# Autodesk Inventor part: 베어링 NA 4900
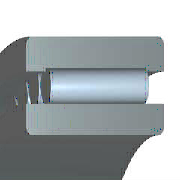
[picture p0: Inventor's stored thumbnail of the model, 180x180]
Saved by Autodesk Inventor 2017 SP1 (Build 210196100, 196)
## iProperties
Created: 2021-07
Part Number: 베어링 NA 4900
Material: 강철, 연강
Description: 니들 롤러 베어링 - 경계 치수 및 공차
Document SubType Name: Modeling
Standard: KS B 2029
Designer: mdu
Standards Organization: KS
Language: ko-KR
Size Designation: NA 4900 - 10 x 22 x 13
Categories: <MemberInstance><Categories><Category DisplayName="샤프트 부품" InternalName="7f7aeb1f-a693-4053-b835-cee3144e0d98" Mnemonic="SHFT"><Category DisplayName="베어링" Inter
Density: 7.86 g/cm^3
Mass: 23.8213 g
Surface Area: 38.613 cm^2
Volume: 3.0307 cm^3
Appearance: 베이지색
IsCustomPart: 0
Author: mdu
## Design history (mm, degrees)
sketch "스케치"
  geometry: L1 (1.857, 9)-(11.143, 9); L2 (11.143, 9)-(11.143, 7); L3 (13, 7)-(0, 7); L4 (1.857, 7)-(1.857, 9); L5 (1.857, 8)-(11.143, 8); L6 (6.5, 8)-(6.5, 7); L7 (0, 5)-(13, 5); L8 (0, 11)-(13, 11); L9 (13, 5)-(13, 7); L10 (13, 8.8)-(13, 11); L11 (1.857, 8.8)-(0, 8.8); L12 (11.143, 8.8)-(13, 8.8); L13 (-6, 0)-(36, 0) reference; L14 (0, -1.9)-(0, 14.9) reference
  constraints: 24 end point, 8 point on line, 3 midpoint, 3 parallel, 3 perpendicular, 2 symmetric about line, 1 horizontal, 1 other
  dimensions: "d6" = 10 diameter of L7 L13 (= WD); "d7" = 14 diameter of L3 L13 (= KID1); "d8" = 22 diameter of L8 L13 (= BD); "d9" = 16 diameter of L6.start L13 (= 0.5 x WD + 0.5 x BD); "d10" = 17.6 diameter of L12 L13 (= 0.9 x BD + 0.9 x WD - 0.8 x KID1); "d11" = 18 diameter of L1 L13 (= BD + WD - KID1); "d12" = 1.85714 distance between parallel lines of L14 L4 (= 0.142857 x KB); "d13" = 13 distance between parallel lines of L14 L9 (= KB); "d14" = 11.14286 distance between parallel lines of L14 L2 (= 0.857143 x KB)
revolve "본체" stored, may be unused: angle "d17" = 90 deg
revolve "롤러" stored, may be unused: angle "d18" = 90 deg
pattern_circular "IDS_ARRAYROLLER[SIMPL:T]" dims angle "d2" = 360 deg
body "Solid1"
fillet "모깎기1" dims "d0" = 0.3 (= KRS)
other parameters: "WD" = 10 [user parameter; used in 6 equation terms], "BD" = 22 [user parameter; used in 6 equation terms], "KB" = 13 [user parameter; used in 3 equation terms], "KID1" = 14 [user parameter; used in 4 equation terms], "KRS" = 0.3 [user parameter; used in 1 equation term], "d3" = 0, "d4" = 0, "d5" = 0, "d15" = 0, "d16" = 0, "BC0" = 9150000 [user parameter], "WR" = 5 (= 0.5 x WD) [user parameter], "BBA" = 0 [user parameter], "BC" = 8150000 [user parameter], "BR" = 11 (= 0.5 x BD) [user parameter]
